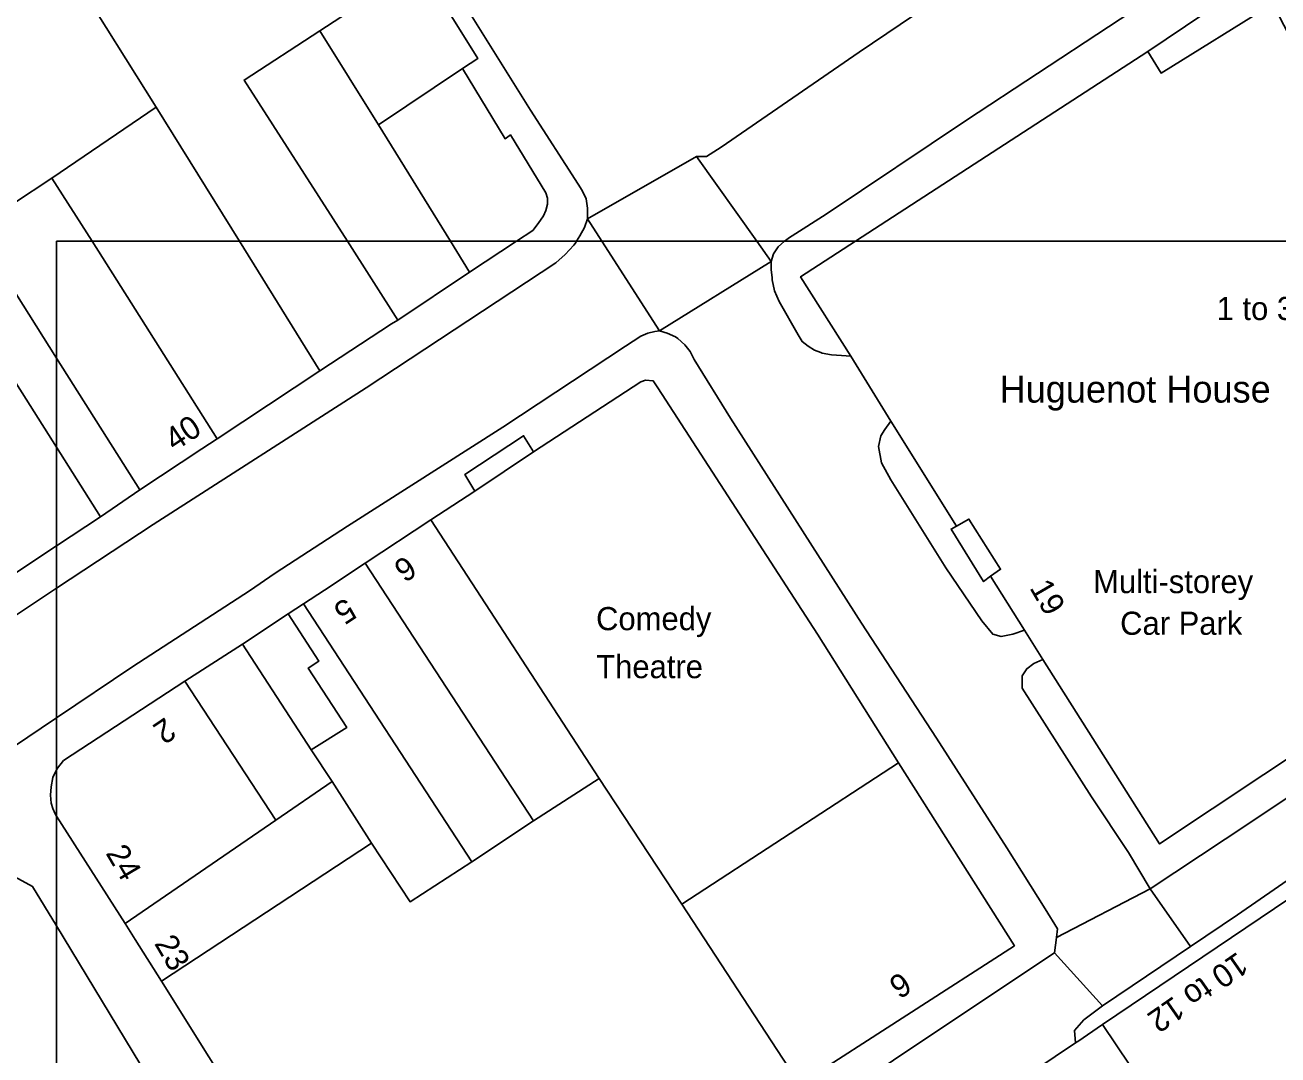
# Model space of a CAD drawing. Extents: x 529240 to 530363, y 179600 to 180767.
# Drawn here: x 529714 to 529795.1, y 180561.3 to 180628 of the extents above; entities that cross this region are included whole.
import ezdxf

# ---------------------------------------------------------------- set-up
doc = ezdxf.new("R2010")
doc.units = 0
for name, color, linetype in [('Building', 7, 'Continuous'), ('Road Or Track', 7, 'Continuous'), ('Roadside', 7, 'Continuous'), ('Unclassified', 7, 'Continuous')]:
    doc.layers.add(name, color=color, linetype=linetype)

msp = doc.modelspace()

# ---------------------------------------------------------------- linework, layer by layer
at = {"layer": 'Building'}
for points in [[(529727.843, 180614), (529734.837, 180614), (529728.15, 180624.45), (529733.05, 180627.65), (529738.5, 180631.2), (529737.6, 180632.6), (529733.7, 180638.7), (529732.6, 180640.55), (529723.5, 180634.9), (529719.5, 180632.4), (529717.25, 180631), (529722.45, 180622.7)], [(529767.745, 180614), (529801.253, 180614), (529800.75, 180614.7), (529798, 180618.4), (529799.75, 180619.75), (529794.8, 180629.4), (529787.55, 180624.9), (529786.7, 180626.3)], [(529734.837, 180614), (529741.514, 180614), (529736.85, 180621.55), (529733.05, 180627.65), (529728.15, 180624.45)], [(529741.514, 180614), (529745.787, 180614), (529746.85, 180614.7), (529747.2, 180615.15), (529747.55, 180615.65), (529747.7, 180616), (529747.8, 180616.4), (529747.8, 180616.8), (529747.7, 180617.15), (529745.4, 180620.9), (529745.05, 180620.65), (529742.3, 180625.2), (529736.85, 180621.55)], [(529718.296, 180614), (529727.843, 180614), (529722.45, 180622.7), (529715.7, 180618.1)], [(529716, 180606.429), (529716, 180614), (529718.296, 180614), (529715.7, 180618.1), (529710.7, 180614.8)], [(529716, 180600.662), (529716, 180606.429), (529710.7, 180614.8), (529710.3, 180614.55), (529708.15, 180613.1), (529712.85, 180605.65)], [(529716, 180606.429), (529721.4, 180597.9), (529725.4, 180600.55), (529726.4, 180601.2), (529718.296, 180614), (529716, 180614)], [(529718.296, 180614), (529726.4, 180601.2), (529733.05, 180605.6), (529727.843, 180614)], [(529727.843, 180614), (529733.05, 180605.6), (529737.7, 180608.65), (529738.1, 180608.9), (529734.837, 180614)], [(529734.837, 180614), (529738.1, 180608.9), (529742.75, 180612), (529741.514, 180614)], [(529741.514, 180614), (529742.75, 180612), (529745.787, 180614)], [(529767.745, 180614), (529764.2, 180611.7), (529767.45, 180606.55), (529770.05, 180602.35), (529774.3, 180595.55), (529775.1, 180596), (529777.15, 180592.75), (529776.5, 180592.3), (529778.7, 180588.8), (529779.9, 180586.9), (529787.45, 180574.95), (529811.2, 180590.75), (529812.75, 180594.3), (529806.45, 180605.6), (529805.45, 180607.3), (529804.25, 180609.5), (529803.5, 180610.9), (529804.15, 180611.2), (529802.9, 180613.6), (529801.9, 180613.1), (529801.253, 180614)], [(529716, 180600.662), (529718.85, 180596.15), (529721.4, 180597.9), (529716, 180606.429)], [(529716, 180594.261), (529716, 180600.662), (529712.85, 180605.65), (529702.25, 180598.5), (529707.2, 180591.05), (529710.1, 180590.35)], [(529746.9, 180600.35), (529743.1, 180597.8), (529740.25, 180595.95), (529751.15, 180579.2), (529756.5, 180571.05), (529770.55, 180580.2), (529765.3, 180588.55), (529754.95, 180604.5), (529754.65, 180604.95), (529754.15, 180605), (529753.85, 180604.9)], [(529743.1, 180597.8), (529746.9, 180600.35), (529746.25, 180601.4), (529742.45, 180598.9)], [(529716, 180594.261), (529718.85, 180596.15), (529716, 180600.662)], [(529736, 180593.15), (529746.9, 180576.45), (529751.15, 180579.2), (529740.25, 180595.95)], [(529776.5, 180592.3), (529777.15, 180592.75), (529775.1, 180596), (529774.3, 180595.55), (529773.95, 180595.35), (529776.05, 180591.95)], [(529732, 180590.5), (529742.9, 180573.8), (529746.9, 180576.45), (529736, 180593.15), (529733.35, 180591.4)], [(529731, 180589.85), (529733, 180586.8), (529732.3, 180586.35), (529734.8, 180582.5), (529732.5, 180581.05), (529733.85, 180579), (529736.4, 180575), (529738.9, 180571.2), (529742.9, 180573.8), (529732, 180590.5)], [(529728.05, 180587.9), (529732.5, 180581.05), (529734.8, 180582.5), (529732.3, 180586.35), (529733, 180586.8), (529731, 180589.85)], [(529730.2, 180576.5), (529733.85, 180579), (529732.5, 180581.05), (529728.05, 180587.9), (529724.3, 180585.5)], [(529716, 180576.744), (529720.45, 180569.8), (529730.2, 180576.5), (529724.3, 180585.5), (529716.45, 180580.35), (529716.05, 180579.85), (529716, 180579.75)], [(529763.4, 180560.5), (529764.1, 180559.35), (529778.05, 180568.35), (529770.55, 180580.2), (529756.5, 180571.05)], [(529716, 180576.744), (529716, 180579.75), (529715.75, 180579.25), (529715.65, 180578.65), (529715.6, 180578.1), (529715.65, 180577.6), (529715.75, 180577.25), (529715.9, 180576.9)], [(529722.8, 180566.05), (529732, 180551.35), (529737.85, 180541.9), (529759.8, 180556.45), (529759.1, 180557.65), (529760.95, 180558.85), (529763.4, 180560.5), (529756.5, 180571.05), (529751.15, 180579.2), (529746.9, 180576.45), (529742.9, 180573.8), (529738.9, 180571.2), (529736.4, 180575)], [(529736.4, 180575), (529733.85, 180579), (529730.2, 180576.5), (529720.45, 180569.8), (529721.1, 180568.75), (529722.8, 180566.05)], [(529806.15, 180563.55), (529799.55, 180573.9), (529783.75, 180563.25), (529790.85, 180552.7), (529791, 180552.45), (529794.3, 180554.9), (529794, 180555.35), (529798.05, 180558.1)], [(529790.85, 180552.7), (529783.75, 180563.25), (529782.15, 180562.15), (529782, 180562.05), (529778.13, 180559.44), (529785.42, 180548.59), (529786.1, 180549.05), (529785.9, 180549.35)]]:
    msp.add_lwpolyline(points, close=True, dxfattribs=at)
for points in [[(529734.837, 180614), (529728.15, 180624.45), (529733.05, 180627.65)], [(529786.7, 180626.3), (529767.745, 180614)], [(529742.3, 180625.2), (529745.05, 180620.65), (529745.4, 180620.9), (529747.7, 180617.15), (529747.8, 180616.8), (529747.8, 180616.4), (529747.7, 180616), (529747.55, 180615.65), (529747.2, 180615.15), (529746.85, 180614.7), (529745.787, 180614)], [(529722.45, 180622.7), (529727.843, 180614)], [(529736.85, 180621.55), (529741.514, 180614)], [(529718.296, 180614), (529715.7, 180618.1)], [(529710.7, 180614.8), (529716, 180606.429)], [(529726.4, 180601.2), (529718.296, 180614)], [(529727.843, 180614), (529733.05, 180605.6)], [(529738.1, 180608.9), (529734.837, 180614)], [(529741.514, 180614), (529742.75, 180612)], [(529745.787, 180614), (529742.75, 180612)], [(529767.745, 180614), (529764.2, 180611.7), (529767.45, 180606.55)], [(529742.75, 180612), (529738.1, 180608.9)], [(529738.1, 180608.9), (529737.7, 180608.65), (529733.05, 180605.6)], [(529716, 180606.429), (529721.4, 180597.9)], [(529767.45, 180606.55), (529770.05, 180602.35)], [(529712.85, 180605.65), (529716, 180600.662)], [(529733.05, 180605.6), (529726.4, 180601.2)], [(529770.55, 180580.2), (529765.3, 180588.55), (529754.95, 180604.5), (529754.65, 180604.95), (529754.15, 180605), (529753.85, 180604.9), (529746.9, 180600.35)], [(529770.05, 180602.35), (529774.3, 180595.55)], [(529726.4, 180601.2), (529725.4, 180600.55), (529721.4, 180597.9)], [(529716, 180600.662), (529718.85, 180596.15)], [(529746.9, 180600.35), (529743.1, 180597.8)], [(529716, 180594.261), (529710.1, 180590.35), (529707.2, 180591.05), (529702.25, 180598.5)], [(529721.4, 180597.9), (529718.85, 180596.15)], [(529743.1, 180597.8), (529740.25, 180595.95)], [(529718.85, 180596.15), (529716, 180594.261)], [(529740.25, 180595.95), (529736, 180593.15)], [(529740.25, 180595.95), (529751.15, 180579.2)], [(529774.3, 180595.55), (529775.1, 180596)], [(529775.1, 180596), (529777.15, 180592.75), (529776.5, 180592.3)], [(529736, 180593.15), (529733.35, 180591.4), (529732, 180590.5)], [(529736, 180593.15), (529746.9, 180576.45)], [(529776.5, 180592.3), (529778.7, 180588.8)], [(529732, 180590.5), (529731, 180589.85)], [(529732, 180590.5), (529742.9, 180573.8)], [(529779.9, 180586.9), (529787.45, 180574.95), (529811.2, 180590.75)], [(529731, 180589.85), (529728.05, 180587.9)], [(529731, 180589.85), (529733, 180586.8), (529732.3, 180586.35), (529734.8, 180582.5), (529732.5, 180581.05)], [(529778.7, 180588.8), (529779.9, 180586.9)], [(529728.05, 180587.9), (529724.3, 180585.5)], [(529728.05, 180587.9), (529732.5, 180581.05)], [(529724.3, 180585.5), (529716.45, 180580.35), (529716.05, 180579.85), (529716, 180579.75)], [(529724.3, 180585.5), (529730.2, 180576.5)], [(529732.5, 180581.05), (529733.85, 180579)], [(529756.5, 180571.05), (529770.55, 180580.2)], [(529764.1, 180559.35), (529778.05, 180568.35), (529770.55, 180580.2)], [(529716, 180579.75), (529715.75, 180579.25), (529715.65, 180578.65), (529715.6, 180578.1), (529715.65, 180577.6), (529715.75, 180577.25), (529715.9, 180576.9), (529716, 180576.744)], [(529746.9, 180576.45), (529751.15, 180579.2)], [(529751.15, 180579.2), (529756.5, 180571.05)], [(529733.85, 180579), (529730.2, 180576.5)], [(529733.85, 180579), (529736.4, 180575)], [(529716, 180576.744), (529720.45, 180569.8)], [(529730.2, 180576.5), (529720.45, 180569.8)], [(529742.9, 180573.8), (529746.9, 180576.45)], [(529736.4, 180575), (529722.8, 180566.05)], [(529736.4, 180575), (529738.9, 180571.2), (529742.9, 180573.8)], [(529783.75, 180563.25), (529799.55, 180573.9)], [(529756.5, 180571.05), (529763.4, 180560.5)], [(529720.45, 180569.8), (529721.1, 180568.75), (529722.8, 180566.05)], [(529722.8, 180566.05), (529732, 180551.35), (529737.85, 180541.9), (529759.8, 180556.45), (529759.1, 180557.65), (529760.95, 180558.85)], [(529782, 180562.05), (529782.15, 180562.15), (529783.75, 180563.25)], [(529783.75, 180563.25), (529790.85, 180552.7)], [(529778.13, 180559.44), (529782, 180562.05)]]:
    msp.add_lwpolyline(points, dxfattribs=at)
at = {"layer": 'Road Or Track'}
for points in [[(529761.373, 180614), (529763.15, 180614), (529763.55, 180614.3), (529763.65, 180614.35), (529765.85, 180615.75), (529774.95, 180621.85), (529784.15, 180627.9), (529792.95, 180633.7), (529793.7, 180633.95), (529793.87, 180633.97), (529789.3, 180640.75), (529788.55, 180640.15), (529785.65, 180638.2), (529768, 180626.25), (529759.05, 180620.1), (529758.1, 180619.5), (529757.45, 180619.5)], [(529751.33, 180614), (529761.373, 180614), (529757.45, 180619.5), (529750.4, 180615.45)], [(529751.33, 180614), (529750.4, 180615.45), (529750.2, 180614.9), (529749.9, 180614.35), (529749.69, 180614)], [(529716, 180583.122), (529720.95, 180586.45), (529728.5, 180591.35), (529730.15, 180592.5), (529734.85, 180595.55), (529744.9, 180601.95), (529752.85, 180607.2), (529753.85, 180607.85), (529754.3, 180608.05), (529754.75, 180608.15), (529755.05, 180608.2), (529751.33, 180614), (529749.69, 180614), (529749.6, 180613.85), (529749.5, 180613.75), (529748.95, 180613.15), (529748.35, 180612.6), (529736.05, 180604.5), (529722.25, 180595.65), (529716, 180591.524)], [(529751.33, 180614), (529755.05, 180608.2), (529762.3, 180612.7), (529761.373, 180614)], [(529761.373, 180614), (529762.3, 180612.7), (529762.45, 180613.2), (529762.75, 180613.65), (529763.15, 180614)], [(529767.45, 180606.55), (529766.85, 180606.6), (529766.2, 180606.65), (529765.6, 180606.75), (529765.5, 180606.8), (529765.1, 180606.95), (529764.7, 180607.2), (529764.3, 180607.5), (529764.05, 180607.95), (529762.8, 180610.1), (529762.5, 180610.8), (529762.35, 180611.5), (529762.35, 180611.65), (529762.3, 180612.15), (529762.3, 180612.7), (529755.05, 180608.2), (529755.55, 180608.05), (529756.1, 180607.8), (529756.25, 180607.7), (529756.7, 180607.3), (529757.05, 180606.85), (529757.3, 180606.35), (529759.65, 180602.55), (529768.15, 180589.25), (529773, 180581.8), (529777.55, 180574.7), (529780.05, 180570.75), (529780.85, 180569.45), (529780.78, 180568.88), (529786.85, 180572.05), (529785.45, 180574.4), (529783.05, 180578), (529778.55, 180585.05), (529778.55, 180585.85), (529778.85, 180586.3), (529779.3, 180586.65), (529779.9, 180586.9), (529778.7, 180588.8), (529777.95, 180588.55), (529777.2, 180588.4), (529776.65, 180588.55), (529775.95, 180589.4), (529773.6, 180592.85), (529770.05, 180598.55), (529769.45, 180599.65), (529769.25, 180600.7), (529769.4, 180601.4), (529769.65, 180601.8), (529770.05, 180602.35)], [(529819.5, 180588.94), (529816.15, 180593.75), (529816.15, 180593.1), (529816.05, 180592.55), (529815.9, 180592.1), (529815.65, 180591.6), (529815.3, 180591.05), (529814.8, 180590.65), (529814.35, 180590.3), (529810.9, 180588.05), (529791.7, 180575.25), (529786.85, 180572.05), (529789.46, 180568.3), (529792.5, 180570.35), (529803.4, 180577.9), (529805.2, 180579.55), (529813.95, 180585.2), (529818.5, 180588.3)], [(529716, 180583.122), (529716, 180591.524), (529711.95, 180588.85), (529708.3, 180586.4), (529708.1, 180586.2), (529707.65, 180585.8), (529707.2, 180585.5), (529706.65, 180585.35), (529706.15, 180585.25), (529705.65, 180585.3), (529710.5, 180577.9), (529710.6, 180578.4), (529710.65, 180578.55), (529710.85, 180579.05), (529711.15, 180579.5), (529711.55, 180580.05), (529712.35, 180580.65), (529715, 180582.45)], [(529716, 180537.288), (529716, 180569.641), (529714.45, 180572.2), (529713.05, 180572.95), (529711, 180576.3), (529710.55, 180577.25), (529710.5, 180577.9), (529702.5, 180573.56), (529704, 180571), (529704, 180570.6), (529703.5, 180570.45), (529703.25, 180570.35), (529702.7, 180571), (529696.94, 180567.73), (529697.4, 180567.65), (529697.5, 180567.6), (529698, 180567.3), (529698.5, 180566.9), (529698.85, 180566.4), (529698.9, 180566.3), (529703.3, 180558.95), (529708.8, 180549.4), (529713.4, 180541.55)], [(529780.65, 180567.9), (529783.75, 180564.45), (529789.46, 180568.3), (529786.85, 180572.05), (529780.78, 180568.88)], [(529716, 180537.288), (529718.25, 180533.6), (529720.45, 180529.92), (529734.6, 180538.55), (529728.75, 180548.3), (529721.9, 180559.9), (529716, 180569.641)], [(529736.4, 180533.9), (529737.25, 180534.65), (529743.3, 180538.55), (529755.2, 180546.5), (529757.25, 180546.8), (529761.2, 180549.35), (529773.25, 180557.3), (529774.6, 180557.05), (529778.13, 180559.44), (529782, 180562.05), (529781.95, 180562.85), (529782.55, 180563.55), (529783.75, 180564.45), (529780.65, 180567.9), (529772.25, 180562.3), (529760, 180554.1), (529759.3, 180554.1), (529755.2, 180551.4), (529754.55, 180550.55), (529737.4, 180539.3), (529736.15, 180538.5), (529734.6, 180538.55)]]:
    msp.add_lwpolyline(points, close=True, dxfattribs=at)
for points in [[(529763.15, 180614), (529763.55, 180614.3), (529763.65, 180614.35), (529765.85, 180615.75), (529774.95, 180621.85), (529784.15, 180627.9), (529792.95, 180633.7), (529793.7, 180633.95), (529793.87, 180633.97)], [(529749.69, 180614), (529749.9, 180614.35), (529750.2, 180614.9), (529750.4, 180615.45)], [(529716, 180591.524), (529722.25, 180595.65), (529736.05, 180604.5), (529748.35, 180612.6), (529748.95, 180613.15), (529749.5, 180613.75), (529749.6, 180613.85), (529749.69, 180614)], [(529762.3, 180612.7), (529762.45, 180613.2), (529762.75, 180613.65), (529763.15, 180614)], [(529767.45, 180606.55), (529766.85, 180606.6), (529766.2, 180606.65), (529765.6, 180606.75), (529765.5, 180606.8), (529765.1, 180606.95), (529764.7, 180607.2), (529764.3, 180607.5), (529764.05, 180607.95), (529762.8, 180610.1), (529762.5, 180610.8), (529762.35, 180611.5), (529762.35, 180611.65), (529762.3, 180612.15), (529762.3, 180612.7)], [(529716, 180583.122), (529720.95, 180586.45), (529728.5, 180591.35), (529730.15, 180592.5), (529734.85, 180595.55), (529744.9, 180601.95), (529752.85, 180607.2), (529753.85, 180607.85), (529754.3, 180608.05), (529754.75, 180608.15), (529755.05, 180608.2)], [(529755.05, 180608.2), (529755.55, 180608.05), (529756.1, 180607.8), (529756.25, 180607.7), (529756.7, 180607.3), (529757.05, 180606.85), (529757.3, 180606.35), (529759.65, 180602.55), (529768.15, 180589.25), (529773, 180581.8), (529777.55, 180574.7), (529780.05, 180570.75), (529780.85, 180569.45), (529780.78, 180568.88)], [(529778.7, 180588.8), (529777.95, 180588.55), (529777.2, 180588.4), (529776.65, 180588.55), (529775.95, 180589.4), (529773.6, 180592.85), (529770.05, 180598.55), (529769.45, 180599.65), (529769.25, 180600.7), (529769.4, 180601.4), (529769.65, 180601.8), (529770.05, 180602.35)], [(529816.15, 180593.75), (529816.15, 180593.1), (529816.05, 180592.55), (529815.9, 180592.1), (529815.65, 180591.6), (529815.3, 180591.05), (529814.8, 180590.65), (529814.35, 180590.3), (529810.9, 180588.05), (529791.7, 180575.25), (529786.85, 180572.05)], [(529705.65, 180585.3), (529706.15, 180585.25), (529706.65, 180585.35), (529707.2, 180585.5), (529707.65, 180585.8), (529708.1, 180586.2), (529708.3, 180586.4), (529711.95, 180588.85), (529716, 180591.524)], [(529789.46, 180568.3), (529792.5, 180570.35), (529803.4, 180577.9), (529805.2, 180579.55), (529813.95, 180585.2), (529818.5, 180588.3), (529819.5, 180588.94)], [(529786.85, 180572.05), (529785.45, 180574.4), (529783.05, 180578), (529778.55, 180585.05), (529778.55, 180585.85), (529778.85, 180586.3), (529779.3, 180586.65), (529779.9, 180586.9)], [(529710.5, 180577.9), (529710.6, 180578.4), (529710.65, 180578.55), (529710.85, 180579.05), (529711.15, 180579.5), (529711.55, 180580.05), (529712.35, 180580.65), (529715, 180582.45), (529716, 180583.122)], [(529716, 180569.641), (529714.45, 180572.2)], [(529734.6, 180538.55), (529728.75, 180548.3), (529721.9, 180559.9), (529716, 180569.641)], [(529780.78, 180568.88), (529780.65, 180567.9)], [(529780.65, 180567.9), (529772.25, 180562.3), (529760, 180554.1), (529759.3, 180554.1), (529755.2, 180551.4), (529754.55, 180550.55), (529737.4, 180539.3), (529736.15, 180538.5), (529734.6, 180538.55)], [(529783.75, 180564.45), (529789.46, 180568.3)], [(529782, 180562.05), (529781.95, 180562.85), (529782.55, 180563.55), (529783.75, 180564.45)]]:
    msp.add_lwpolyline(points, dxfattribs=at)
at = {"layer": 'Roadside'}
for points in [[(529739.5, 180631.95), (529743.3, 180625.85), (529742.3, 180625.2), (529745.05, 180620.65), (529745.4, 180620.9), (529747.7, 180617.15), (529747.8, 180616.8), (529747.8, 180616.4), (529747.7, 180616), (529747.55, 180615.65), (529747.2, 180615.15), (529746.85, 180614.7), (529745.787, 180614), (529749.69, 180614), (529749.9, 180614.35), (529750.2, 180614.9), (529750.4, 180615.45), (529750.4, 180616.15), (529750.3, 180616.75), (529750.05, 180617.3), (529749.8, 180617.7), (529746.7, 180622.5), (529739.9, 180633.4)], [(529795.28, 180633.87), (529794.1, 180634), (529793.87, 180633.97), (529793.7, 180633.95), (529792.95, 180633.7), (529784.15, 180627.9), (529774.95, 180621.85), (529765.85, 180615.75), (529763.65, 180614.35), (529763.55, 180614.3), (529763.15, 180614), (529767.745, 180614), (529786.7, 180626.3), (529793.95, 180631.2), (529794.8, 180629.4), (529799.75, 180619.75)], [(529760, 180554.1), (529772.25, 180562.3), (529780.65, 180567.9), (529780.78, 180568.88), (529780.85, 180569.45), (529780.05, 180570.75), (529777.55, 180574.7), (529773, 180581.8), (529768.15, 180589.25), (529759.65, 180602.55), (529757.3, 180606.35), (529757.05, 180606.85), (529756.7, 180607.3), (529756.25, 180607.7), (529756.1, 180607.8), (529755.55, 180608.05), (529755.05, 180608.2), (529754.75, 180608.15), (529754.3, 180608.05), (529753.85, 180607.85), (529752.85, 180607.2), (529744.9, 180601.95), (529734.85, 180595.55), (529730.15, 180592.5), (529728.5, 180591.35), (529720.95, 180586.45), (529716, 180583.122), (529716, 180579.75), (529716.05, 180579.85), (529716.45, 180580.35), (529724.3, 180585.5), (529728.05, 180587.9), (529731, 180589.85), (529732, 180590.5), (529733.35, 180591.4), (529736, 180593.15), (529740.25, 180595.95), (529743.1, 180597.8), (529742.45, 180598.9), (529746.25, 180601.4), (529746.9, 180600.35), (529753.85, 180604.9), (529754.15, 180605), (529754.65, 180604.95), (529754.95, 180604.5), (529765.3, 180588.55), (529770.55, 180580.2), (529778.05, 180568.35), (529764.1, 180559.35)], [(529711.95, 180588.85), (529716, 180591.524), (529716, 180594.261), (529710.1, 180590.35)], [(529811.2, 180590.75), (529787.45, 180574.95), (529779.9, 180586.9), (529779.3, 180586.65), (529778.85, 180586.3), (529778.55, 180585.85), (529778.55, 180585.05), (529783.05, 180578), (529785.45, 180574.4), (529786.85, 180572.05), (529791.7, 180575.25), (529810.9, 180588.05)], [(529803.4, 180577.9), (529792.5, 180570.35), (529789.46, 180568.3), (529783.75, 180564.45), (529782.55, 180563.55), (529781.95, 180562.85), (529782, 180562.05), (529782.15, 180562.15), (529783.75, 180563.25), (529799.55, 180573.9)], [(529732, 180551.35), (529722.8, 180566.05), (529721.1, 180568.75), (529720.45, 180569.8), (529716, 180576.744), (529716, 180569.641), (529721.9, 180559.9)]]:
    msp.add_lwpolyline(points, dxfattribs=at)
for points in [[(529716, 180591.524), (529722.25, 180595.65), (529736.05, 180604.5), (529748.35, 180612.6), (529748.95, 180613.15), (529749.5, 180613.75), (529749.6, 180613.85), (529749.69, 180614), (529745.787, 180614), (529742.75, 180612), (529738.1, 180608.9), (529737.7, 180608.65), (529733.05, 180605.6), (529726.4, 180601.2), (529725.4, 180600.55), (529721.4, 180597.9), (529718.85, 180596.15), (529716, 180594.261)], [(529763.15, 180614), (529762.75, 180613.65), (529762.45, 180613.2), (529762.3, 180612.7), (529762.3, 180612.15), (529762.35, 180611.65), (529762.35, 180611.5), (529762.5, 180610.8), (529762.8, 180610.1), (529764.05, 180607.95), (529764.3, 180607.5), (529764.7, 180607.2), (529765.1, 180606.95), (529765.5, 180606.8), (529765.6, 180606.75), (529766.2, 180606.65), (529766.85, 180606.6), (529767.45, 180606.55), (529764.2, 180611.7), (529767.745, 180614)], [(529770.05, 180602.35), (529769.65, 180601.8), (529769.4, 180601.4), (529769.25, 180600.7), (529769.45, 180599.65), (529770.05, 180598.55), (529773.6, 180592.85), (529775.95, 180589.4), (529776.65, 180588.55), (529777.2, 180588.4), (529777.95, 180588.55), (529778.7, 180588.8), (529776.5, 180592.3), (529776.05, 180591.95), (529773.95, 180595.35), (529774.3, 180595.55)], [(529716, 180569.641), (529716, 180576.744), (529715.9, 180576.9), (529715.75, 180577.25), (529715.65, 180577.6), (529715.6, 180578.1), (529715.65, 180578.65), (529715.75, 180579.25), (529716, 180579.75), (529716, 180583.122), (529715, 180582.45), (529712.35, 180580.65), (529711.55, 180580.05), (529711.15, 180579.5), (529710.85, 180579.05), (529710.65, 180578.55), (529710.6, 180578.4), (529710.5, 180577.9), (529710.55, 180577.25), (529711, 180576.3), (529713.05, 180572.95), (529714.45, 180572.2)]]:
    msp.add_lwpolyline(points, close=True, dxfattribs=at)
at = {"layer": 'Unclassified'}
for points in [[(529761.373, 180614), (529757.45, 180619.5)], [(529751.33, 180614), (529750.4, 180615.45)], [(529755.05, 180608.2), (529751.33, 180614)], [(529762.3, 180612.7), (529761.373, 180614)], [(529755.05, 180608.2), (529762.3, 180612.7)], [(529743.1, 180597.8), (529742.45, 180598.9), (529746.25, 180601.4), (529746.9, 180600.35)], [(529776.5, 180592.3), (529776.05, 180591.95), (529773.95, 180595.35), (529774.3, 180595.55)], [(529780.78, 180568.88), (529786.85, 180572.05)], [(529786.85, 180572.05), (529789.46, 180568.3)], [(529780.65, 180567.9), (529783.75, 180564.45)]]:
    msp.add_lwpolyline(points, dxfattribs=at)

# ---------------------------------------------------------------- texts
for s, height, p in [('1 to 35', 1.5, (529791.15, 180608.9)), ('Huguenot House', 1.75, (529777.09, 180603.55)), ('Multi-storey', 1.5, (529783.15, 180591.2)), ('Comedy', 1.5, (529750.95, 180588.8)), ('Car Park', 1.5, (529784.9, 180588.5)), ('Theatre', 1.5, (529750.96, 180585.69))]:
    msp.add_text(s, height=height, dxfattribs=at).set_placement(p)
for s, rotation, p in [('40', 33.5, (529723.65, 180600.35)), ('6', 213.7, (529738.65, 180593.7)), ('19', 300.2, (529779, 180591.55)), ('5', 213.3, (529734.75, 180590.95)), ('2', 214.2, (529723.05, 180583.2)), ('24', 300.5, (529719.15, 180574.35)), ('23', 300.5, (529722.3, 180568.5)), ('10 to 12', 214.8, (529792.5, 180568)), ('9', 32.5, (529770.6, 180564.85))]:
    msp.add_text(s, height=1.5, rotation=rotation, dxfattribs=at).set_placement(p)

doc.saveas('drawing.dxf')
